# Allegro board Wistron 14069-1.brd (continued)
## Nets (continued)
M_B_DQS_DP2: CPU1.AP33 DIMM2.175 DIMM4.175
M_B_DQS_DP3: CPU1.AN28 DIMM2.186 DIMM4.186
M_B_DQS_DP4: CPU1.AN12 DIMM2.245 DIMM4.245
M_B_DQS_DP5: CPU1.AP8 DIMM2.256 DIMM4.256
M_B_DQS_DP6: CPU1.AL8 DIMM2.267 DIMM4.267
M_B_DQS_DP7: CPU1.AG7 DIMM2.278 DIMM4.278
M_B_ODT0: CPU1.AM16 DIMM4.87
M_B_ODT1: CPU1.AL16 DIMM4.91
M_B_ODT2: CPU1.AP15 DIMM2.87
M_B_ODT3: CPU1.AL15 DIMM2.91
M_BA_A_0: CPU1.AY13 DIMM1.81 DIMM3.81
M_BA_A_1: CPU1.AV15 DIMM1.224 DIMM3.224
M_BA_B_0: CPU1.AL18 DIMM2.81 DIMM4.81
M_BA_B_1: CPU1.AM18 DIMM2.224 DIMM4.224
M_BG_A_0: CPU1.AW23 DIMM1.63 DIMM3.63
M_BG_A_1: CPU1.AV23 DIMM1.207 DIMM3.207
M_BG_B_0: CPU1.AW28 DIMM2.63 DIMM4.63
M_BG_B_1: CPU1.AY28 DIMM2.207 DIMM4.207
M_PAR_A: CPU1.AY15 DIMM1.222 DIMM3.222
M_PAR_B: CPU1.AL20 DIMM2.222 DIMM4.222
M_VREF_DQ_DIM1: C2.1 C1206.1 CPU1.AC39 R1206.1
ME_CNTL: PCH1.AE44 R1506.1 R2059.1
ME_CNTL_1: Q2005.B R2059.2
ME_CNTL_2: Q2005.E R2060.2
MIC1_JD: AUDR1.3 D3001.2 R3013.1
MIC1_VREFO_L: R3008.1 U2701.28
MIC1_VREFO_R: R3011.1 U2701.32
MIC2-VREFO: D2906.3 U2701.30
MIC2_JD: AUDF1.5 R2909.2
MIC2_L: AUDF1.2 C2936.2 FL2906.2
MIC2_LL: FL2906.1 Q2902.6 R2932.2 R2948.2
MIC2_LL*: Q2902.2 R2950.2
MIC2_R: AUDF1.4 C2934.2 FL2907.2
MIC2_RR: FL2907.1 Q2902.3 R2941.2 R2949.2
MIC2_RR*: Q2902.5 R2951.2
MINI1_WAKE#: NGFFE1.55 R6106.2
MINI_CLKREQ#_WLAN_C: NGFFE1.53 R6107.2
MONO_C_L: C2920.1 R2921.2 SPK1.1
MONO_C_R: C2921.1 R2922.2 SPK1.3
MONO_L: C2735.2 R2921.1
MONO_R: C2736.2 R2922.1
MUTE: Q2704.C R2926.1 R2950.1 R2951.1 R2952.1 R2953.1 R3014.1 R3015.1 R3016.1 R3017.1 R3018.1 R3019.1
MUTE_C: Q2903.C R2920.1 SPK1.7
MUTE_INT: Q2903.B R2926.2
MUTE_R: Q2704.B R2708.2 R2712.1
MUTE_RR: C2721.1 C2722.1 Q2703.E R2708.1
NGFFE_ALERT#: PCH1.R36 R1505.1 R6118.1
NGFFE_ALERT#_R: NGFFE1.62 R6118.2
OC_LED_GREEN_C: LEDH2.11 LEDH2.13 Q23.6 R6424.2
OCL_PCH_N: PCH1.AM44 R472.1 R473.1 R1504.1
OPC_FUSEPRG: CPU1.AB38 TP_CPU13.1
P2402OV_EN: C6214.1 R866.2 R3418.2 U3402.2 U3402.4
PB_IN_N_1: C7921.2 R7976.1 R7977.2 SIO1.75
PCH_CLKRUN_N: PCH1.AW22 R2024.1
PCH_GPIO1: GPIO1.1 PCH1.AL35 R244.1 R813.1
PCH_GPIO2: GPIO2.1 PCH1.AJ39 R243.1 R814.1
PCH_HOT_R_N: PCH1.AT27 R2221.2 R2222.2
PCH_INTRUDER_N: PCH1.BE11 R1510.1
PCH_JTAG_TCK: PCH1.AN3 R2037.2 R9910.1
PCH_JTAG_TDI: PCH1.AP2 R452.2 R2040.1
PCH_JTAG_TDO: PCH1.AP1 R456.2 R2038.1
PCH_JTAG_TMS: PCH1.AR2 R454.2 R2043.1
PCH_JTAGX: PCH1.AR3 R2035.1 R2036.2
PCH_PORT80_LED: PCH1.BB41 R2214.2 R2215.2
PCH_POWER_VIN: PD5101.K PD5102.K PR5102.2 PR5103.2
PCH_PWROK: PCH1.AW11 R474.1 U401.D
PCH_RTCRST_PULLUP: C2006.2 CMOS1.2 PCH1.BC10 R2049.1
PCH_SATA_LED_N: Q6402.2 R1703.2 R6409.2
PCH_SATA_LED_NMOS: Q58.D Q6402.5 Q6402.6 R650.2 R6405.2
PCH_SATA_LED_R_N: PCH1.AD44 R1703.1
PCH_SPKR1: Q2002.B R2008.2
PCH_SRTCRSTB_PULLUP: C2001.2 PCH1.BB10 R2046.2
PCH_SUSCLK_WLAN: NGFFE1.50 R6108.2
PCH_SYSPWROK: C2002.1 D21.3 PCH1.AY1 R2011.2 R2012.2 R2014.2 R9908.1
PCH_WAKE_N: PCH1.BC13 PCIE1.B11 PCIE2.B11 PCIE16.B11 R2030.1 R6106.1 R6211.2
PCIE_RX_CON_N9: NGFFM1.43 R926.1
PCIE_RX_CON_N10: NGFFM1.29 R923.1
PCIE_RX_CON_N11: NGFFM1.17 R921.1
PCIE_RX_CON_N12: NGFFM1.5 R919.1
PCIE_RX_CON_P9: NGFFM1.41 R925.1
PCIE_RX_CON_P10: NGFFM1.31 R924.1
PCIE_RX_CON_P11: NGFFM1.19 R922.1
PCIE_RX_CON_P12: NGFFM1.7 R920.1
PCIE_RX_LAN_N5: C1605.2 U3101.18
PCIE_RX_LAN_P5: C1602.2 U3101.17
PCIE_RX_PCH_N5: C1605.1 PCH1.K19
PCIE_RX_PCH_N6: NGFFE1.43 PCH1.G22
PCIE_RX_PCH_N7: PCH1.L22 PCIE1.A17
PCIE_RX_PCH_N8: PCH1.K24 PCIE2.A17
PCIE_RX_PCH_N9: PCH1.G31 R926.2
PCIE_RX_PCH_N10: PCH1.G29 R923.2
PCIE_RX_PCH_N11: PCH1.L31 R921.2
PCIE_RX_PCH_N12: PCH1.G33 R919.2
PCIE_RX_PCH_P5: C1602.1 PCH1.L19
PCIE_RX_PCH_P6: NGFFE1.41 PCH1.E22
PCIE_RX_PCH_P7: PCH1.K22 PCIE1.A16
PCIE_RX_PCH_P8: PCH1.L24 PCIE2.A16
PCIE_RX_PCH_P9: PCH1.H31 R925.2
PCIE_RX_PCH_P10: PCH1.E29 R924.2
PCIE_RX_PCH_P11: PCH1.K31 R922.2
PCIE_RX_PCH_P12: PCH1.H33 R920.2
PCIE_TX_CON_N6: C1606.1 NGFFE1.37
PCIE_TX_CON_N7: C1607.1 PCIE1.B15
PCIE_TX_CON_N8: C1617.1 PCIE2.B15
PCIE_TX_CON_N9: C473.2 NGFFM1.47
PCIE_TX_CON_N10: C471.2 NGFFM1.35
PCIE_TX_CON_N11: C469.2 NGFFM1.23
PCIE_TX_CON_N12: C467.2 NGFFM1.11
PCIE_TX_CON_P6: C1601.1 NGFFE1.35
PCIE_TX_CON_P7: C1604.1 PCIE1.B14
PCIE_TX_CON_P8: C1618.1 PCIE2.B14
PCIE_TX_CON_P9: C474.2 NGFFM1.49
PCIE_TX_CON_P10: C472.2 NGFFM1.37
PCIE_TX_CON_P11: C470.2 NGFFM1.25
PCIE_TX_CON_P12: C468.2 NGFFM1.13
PCIE_TX_LAN_N5: C1608.1 U3101.14
PCIE_TX_LAN_P5: C1603.1 U3101.13
PCIE_TX_PCH_N5: C1608.2 PCH1.D22
PCIE_TX_PCH_N6: C1606.2 PCH1.B22
PCIE_TX_PCH_N7: C1607.2 PCH1.C23
PCIE_TX_PCH_N8: C1617.2 PCH1.C24
PCIE_TX_PCH_N9: C473.1 PCH1.C31
PCIE_TX_PCH_N10: C471.1 PCH1.C32
PCIE_TX_PCH_N11: C469.1 PCH1.C33
PCIE_TX_PCH_N12: C467.1 PCH1.B35
PCIE_TX_PCH_P5: C1603.2 PCH1.C22
PCIE_TX_PCH_P6: C1601.2 PCH1.A23
PCIE_TX_PCH_P7: C1604.2 PCH1.B23
PCIE_TX_PCH_P8: C1618.2 PCH1.B24
PCIE_TX_PCH_P9: C474.1 PCH1.B31
PCIE_TX_PCH_P10: C472.1 PCH1.B32
PCIE_TX_PCH_P11: C470.1 PCH1.B33
PCIE_TX_PCH_P12: C468.1 PCH1.A35
PCIEX16_PRSNT1_N: PCIE16.A1 R9301.2
PCIEX16_PRSNT2_N: PCIE16.B17 PCIE16.B31 PCIE16.B48 PCIE16.B81 R9304.2
PCIEX16_PRSNT2_R1_N: R1801.1 R1812.1 R9304.1
PCIEX16_PRSNT2_R2_N: PCH1.BD32 R1801.2
PCIRST1#: R7924.2 RN7909.2(A) SIO1.33
PCIRST2#: RN7909.1(A) SIO1.34
PECI_CPU: CPU1.G7 R1701.1 R2475.1
PECI_PCH: C1701.1 PCH1.AL3 R1701.2 R1706.1
PECI_SIO_R: R2475.2 SIO1.55
PEG_CLK1_WLAN: NGFFE1.47 PCH1.L5
PEG_CLK1_WLAN#: NGFFE1.49 PCH1.L7
PEG_CLK2_LAN: PCH1.F2 U3101.15
PEG_CLK2_LAN#: PCH1.D3 U3101.16
PEG_CLK3_SSD: NGFFM1.55 PCH1.G4
PEG_CLK3_SSD#: NGFFM1.53 PCH1.E5
PEG_CLK4_PCH: PCH1.E6 PCIE2.A13
PEG_CLK4_PCH#: PCH1.D5 PCIE2.A14
PEG_CLK5_PCH: PCH1.D7 PCIE1.A13
PEG_CLK5_PCH#: PCH1.D8 PCIE1.A14
PEG_CLK8_PCH: PCH1.W11 PCIE16.A13
PEG_CLK8_PCH#: PCH1.W10 PCIE16.A14
PEG_CLKREQ1_WLAN#: PCH1.AW24 R1809.1 R6107.1
PEG_CLKREQ2_LAN#: PCH1.AT24 R1810.1 R3108.2
PEG_CLKREQ3_M2#: PCH1.BC24 R1811.1 R6212.2
PEG_PCIEX1_CLKREQ5: PCH1.BE25 PCIE1.B17 R1814.1
PEG_PCIEX1_CLKREQ6: PCH1.AT33 PCIE2.B17 R1815.1
PEG_RCOMP_CPU: CPU1.L7 R302.2
PEG_RCOMPN_CPU: PCH1.B18 R1608.1
PEG_RCOMPP_CPU: PCH1.C17 R1608.2
PEG_RX_CPU_N0: CPU1.B7 PCIE16.A17
PEG_RX_CPU_N1: CPU1.C6 PCIE16.A22
PEG_RX_CPU_N2: CPU1.D5 PCIE16.A26
PEG_RX_CPU_N3: CPU1.E4 PCIE16.A30
PEG_RX_CPU_N4: CPU1.F5 PCIE16.A36
PEG_RX_CPU_N5: CPU1.G4 PCIE16.A40
PEG_RX_CPU_N6: CPU1.H5 PCIE16.A44
PEG_RX_CPU_N7: CPU1.J4 PCIE16.A48
PEG_RX_CPU_N8: CPU1.K5 PCIE16.A53
PEG_RX_CPU_N9: CPU1.L4 PCIE16.A57
PEG_RX_CPU_N10: CPU1.M5 PCIE16.A61
PEG_RX_CPU_N11: CPU1.N4 PCIE16.A65
PEG_RX_CPU_N12: CPU1.P5 PCIE16.A69
PEG_RX_CPU_N13: CPU1.R4 PCIE16.A73
PEG_RX_CPU_N14: CPU1.T5 PCIE16.A77
PEG_RX_CPU_N15: CPU1.U4 PCIE16.A81
PEG_RX_CPU_P0: CPU1.B8 PCIE16.A16
PEG_RX_CPU_P1: CPU1.C7 PCIE16.A21
PEG_RX_CPU_P2: CPU1.D6 PCIE16.A25
PEG_RX_CPU_P3: CPU1.E5 PCIE16.A29
PEG_RX_CPU_P4: CPU1.F6 PCIE16.A35
PEG_RX_CPU_P5: CPU1.G5 PCIE16.A39
PEG_RX_CPU_P6: CPU1.H6 PCIE16.A43
PEG_RX_CPU_P7: CPU1.J5 PCIE16.A47
PEG_RX_CPU_P8: CPU1.K6 PCIE16.A52
PEG_RX_CPU_P9: CPU1.L5 PCIE16.A56
PEG_RX_CPU_P10: CPU1.M6 PCIE16.A60
PEG_RX_CPU_P11: CPU1.N5 PCIE16.A64
PEG_RX_CPU_P12: CPU1.P6 PCIE16.A68
PEG_RX_CPU_P13: CPU1.R5 PCIE16.A72
PEG_RX_CPU_P14: CPU1.T6 PCIE16.A76
PEG_RX_CPU_P15: CPU1.U5 PCIE16.A80
PEG_TX_CON_N0: C9303.2 PCIE16.B15
PEG_TX_CON_N1: C9305.2 PCIE16.B20
PEG_TX_CON_N2: C9307.2 PCIE16.B24
PEG_TX_CON_N3: C9309.2 PCIE16.B28
PEG_TX_CON_N4: C9314.2 PCIE16.B34
PEG_TX_CON_N5: C9316.2 PCIE16.B38
PEG_TX_CON_N6: C9318.2 PCIE16.B42
PEG_TX_CON_N7: C9320.2 PCIE16.B46
PEG_TX_CON_N8: C9324.2 PCIE16.B51
PEG_TX_CON_N9: C9326.2 PCIE16.B55
PEG_TX_CON_N10: C9328.2 PCIE16.B59
PEG_TX_CON_N11: C9332.2 PCIE16.B63
PEG_TX_CON_N12: C9334.2 PCIE16.B67
PEG_TX_CON_N13: C9336.2 PCIE16.B71
PEG_TX_CON_N14: C9338.2 PCIE16.B75
PEG_TX_CON_N15: C9340.2 PCIE16.B79
PEG_TX_CON_P0: C9302.2 PCIE16.B14
PEG_TX_CON_P1: C9304.2 PCIE16.B19
PEG_TX_CON_P2: C9306.2 PCIE16.B23
PEG_TX_CON_P3: C9308.2 PCIE16.B27
PEG_TX_CON_P4: C9313.2 PCIE16.B33
PEG_TX_CON_P5: C9315.2 PCIE16.B37
PEG_TX_CON_P6: C9317.2 PCIE16.B41
PEG_TX_CON_P7: C9319.2 PCIE16.B45
PEG_TX_CON_P8: C9323.2 PCIE16.B50
PEG_TX_CON_P9: C9325.2 PCIE16.B54
PEG_TX_CON_P10: C9327.2 PCIE16.B58
PEG_TX_CON_P11: C9331.2 PCIE16.B62
PEG_TX_CON_P12: C9333.2 PCIE16.B66
PEG_TX_CON_P13: C9335.2 PCIE16.B70
PEG_TX_CON_P14: C9337.2 PCIE16.B74
PEG_TX_CON_P15: C9339.2 PCIE16.B78
PEG_TX_CPU_N0: C9303.1 CPU1.A6
PEG_TX_CPU_N1: C9305.1 CPU1.B5
PEG_TX_CPU_N2: C9307.1 CPU1.C4
PEG_TX_CPU_N3: C9309.1 CPU1.D3
PEG_TX_CPU_N4: C9314.1 CPU1.E2
PEG_TX_CPU_N5: C9316.1 CPU1.F3
PEG_TX_CPU_N6: C9318.1 CPU1.G2
PEG_TX_CPU_N7: C9320.1 CPU1.H3
PEG_TX_CPU_N8: C9324.1 CPU1.J2
PEG_TX_CPU_N9: C9326.1 CPU1.K3
PEG_TX_CPU_N10: C9328.1 CPU1.L2
PEG_TX_CPU_N11: C9332.1 CPU1.M3
PEG_TX_CPU_N12: C9334.1 CPU1.N2
PEG_TX_CPU_N13: C9336.1 CPU1.P3
PEG_TX_CPU_N14: C9338.1 CPU1.R1
PEG_TX_CPU_N15: C9340.1 CPU1.T3
PEG_TX_CPU_P0: C9302.1 CPU1.A5
PEG_TX_CPU_P1: C9304.1 CPU1.B4
PEG_TX_CPU_P2: C9306.1 CPU1.C3
PEG_TX_CPU_P3: C9308.1 CPU1.D2
PEG_TX_CPU_P4: C9313.1 CPU1.E1
PEG_TX_CPU_P5: C9315.1 CPU1.F2
PEG_TX_CPU_P6: C9317.1 CPU1.G1
PEG_TX_CPU_P7: C9319.1 CPU1.H2
PEG_TX_CPU_P8: C9323.1 CPU1.J1
PEG_TX_CPU_P9: C9325.1 CPU1.K2
PEG_TX_CPU_P10: C9327.1 CPU1.L1
PEG_TX_CPU_P11: C9331.1 CPU1.M2
PEG_TX_CPU_P12: C9333.1 CPU1.N1
PEG_TX_CPU_P13: C9335.1 CPU1.P2
PEG_TX_CPU_P14: C9337.1 CPU1.R2
PEG_TX_CPU_P15: C9339.1 CPU1.T2
PLT_WLAN_RST_C: NGFFE1.52 R6109.1
PLTRST#_PCH: C9420.1 C9422.1 DBGH1.10 PCIE1.A11 PCIE2.A11 R1521.2 R6109.2 R6213.2 R7939.2 R9302.1 SATAEX1.P2
PLTRST#_PCH_R: PCH1.BB27 R1521.1
PLTRST#_R: PCIE16.A11 R9302.2
PLTRST*_SIO: R7939.1 SIO1.49
PLTRST_CPU_N: CPU1.E7 PCH1.AK2 R9919.1
PLTRST_LAN_N: R3107.2 R7924.1
PLTRST_LAN_N_R: C3113.1 R3107.1 U3101.19
PM_DOWN_CPU: CPU1.D8 R422.2
PM_DOWN_PCH: PCH1.AH2 R422.1
PM_SLP_S3#_3: D4.K R91.2 SIO1.79 TP168.1
PM_SYNC_CPU: CPU1.E8 R1705.2
PM_SYNC_PCH: PCH1.AJ4 R1705.1
PRIM_XDP_JTAG_TCK_R: R9910.2 XDP1.55
PROC_TRIGIN_CPU: CPU1.D1 R2106.2
PROC_TRIGIN_PCH: PCH1.AL2 R2106.1
PROC_TRIGOUT_CPU: CPU1.B3 R902.2
PROC_TRIGOUT_PCH: PCH1.AK1 R902.1
PROCHOT#_CPU: CPU1.C39 R467.2
PROCHOT#_R: PR4678.2 PU4601.23 R421.1 R467.1
PS_ON_N: Q98.G R4303.2 R4305.2 R7919.2 SIO1.76
PWM1: PU4601.52 PU4716.1
PWM1A: PU4601.47 PU4804.1
PWM2: PU4601.51 PU4709.1
PWM2A: PU4601.46 PU4809.1
PWM3: PU4601.53 PU4713.1
PWM4: PU4601.50 PU4719.1
PWM_LED_N_C: Q25.6 R652.1
PWR_2D5V_EN: PR977.2 PU51.5
PWR_2D5V_FB: PC5038.2 PC5039.1 PR5143.2 PR5145.1 PU51.6
PWR_2D5V_FB_N: PC5039.2 PR5146.1
PWR_2D5V_LX: PL12.1 PR302.1 PU51.1 PU51.2 PU51.3
PWR_2D5V_PVIN: PC5033.1 PC5034.1 PR5024.2 PR5025.2 PR5142.1 PU51.9 PU51.10
PWR_2D5V_SNB: PC301.1 PR302.2
PWR_2D5V_SVIN: PC5035.1 PR5142.2 PU51.8
PWR_2D5V_VPP: PC5036.1 PC5037.1 PC5038.1 PL12.2 PR5026.1 PR5027.1 PR5143.1
PWR_+0P95V: PC5301.1 PC5306.1 PC5309.1 PL5301.2 PR5310.1 PR5313.1 PR5314.1 PR5315.1 PR5321.1 TC5301.1
PWR_+0P95V_BOOT: PR5305.1 PU5301.10
PWR_+0P95V_BOOT_R: PC5305.1 PR5305.2
PWR_+0P95V_CS: PR5307.1 PU5301.2
PWR_+0P95V_EN: PC5311.1 PR5301.1 PU5301.3
PWR_+0P95V_FB: PC5309.2 PR5312.2 PR5316.1 PU5301.4
PWR_+0P95V_LGATE: PU5301.6 PU5303.4
PWR_+0P95V_PHASE: PC5305.2 PL5301.1 PR5309.1 PU5301.8 PU5302.1 PU5302.2 PU5302.3 PU5303.5 PU5303.6 PU5303.7 PU5303.8
PWR_+0P95V_RF: PR5308.1 PU5301.5
PWR_+0P95V_SNB: PC5308.1 PR5309.2
PWR_+0P95V_UG_R: PR5306.2 PU5302.4
PWR_+0P95V_UGATE: PR5306.1 PU5301.9
PWR_+0P95V_VCC: PC5307.1 PR5311.1 PU5301.7
PWR_+0P95V_VIN: PC5302.1 PC5303.1 PC5304.1 PC5310.1 PR5302.1 PR5303.1 PU5302.5 PU5302.6 PU5302.7 PU5302.8
PWR_+1V2_DDR: PC5007.1 PG5001.1 PL5001.2 PR5001.1 PR5016.1 PR5017.1 PR5019.1 PR5020.1 PR5021.1 PR5022.1 PR5023.1 TC5002.1 TC5003.1
PWR_+PCH_1V0: PC5101.1 PG5101.1 PL5101.2 PR5101.1 PR5114.1 PR5115.1 PR5116.1 PR5117.1 PT5107.1
PWR_+PCH_1V0_BOOT: PR5106.2 PU5101.10
PWR_+PCH_1V0_BOOT1: PC5105.1 PR5106.1
PWR_+PCH_1V0_CS: PR5109.1 PU5101.2
PWR_+PCH_1V0_EN: PC5111.2 PR5105.2 PR5108.2 PU5101.3
PWR_+PCH_1V0_FB: PC5110.2 PR5113.2 PR5118.1 PU5101.4
PWR_+PCH_1V0_FB1: PC5110.1 PG5101.2 PR5113.1
PWR_+PCH_1V0_LGATE: PU5101.6 PU5103.4
PWR_+PCH_1V0_PG: PC5106.2 PR5104.2 PU5101.1
PWR_+PCH_1V0_PHASE: PC5105.2 PL5101.1 PR5111.1 PU5101.8 PU5102.1 PU5102.2 PU5102.3 PU5103.5 PU5103.6 PU5103.7 PU5103.8
PWR_+PCH_1V0_RF: PR5110.1 PU5101.5
PWR_+PCH_1V0_SNB: PC5108.1 PR5111.2
PWR_+PCH_1V0_UG1: PR5107.2 PU5102.4
PWR_+PCH_1V0_UGATE: PR5107.1 PU5101.9
PWR_+PCH_1V0_VCC: PC5109.1 PR5112.1 PU5101.7
PWR_+PCH_1V0_VIN: PC5102.1 PC5103.1 PR5102.1 PR5103.1 PT5101.1 PU5102.5 PU5102.6 PU5102.7 PU5102.8
PWR_+VCORE_VIN: PC4701.1 PC4702.1 PC4707.1 PC4711.1 PC4716.1 PC4717.1 PC4735.1 PC4736.1 PR4662.1 PR4668.1 PR4706.2 PR4711.2 PR4718.2 PR4720.1 PR4721.1 PR4722.1 PR4723.1 PR4724.1 PR4725.1 PR5456.2 PT4702.1 PT4707.1 PT4708.1 PT4709.1 PU4701.5 PU4701.6 PU4701.7 PU4701.8 PU4702.5 PU4702.6 PU4702.7 PU4702.8 PU4703.5 PU4703.6 PU4703.7 PU4703.8 PU4704.5 PU4704.6 PU4704.7 PU4704.8 PU4708.5 PU4708.6 PU4708.7 PU4708.8 PU4712.5 PU4712.6 PU4712.7 PU4712.8 PU4718.5 PU4718.6 PU4718.7 PU4718.8 PU4721.5 PU4721.6 PU4721.7 PU4721.8
PWR_+VGT_VIN: PC4801.1 PC4803.1 PC4807.1 PC4808.1 PR4802.1 PR4803.1 PR4805.1 PR4806.1 PR4807.1 PR4811.2 PR4817.2 PT4802.1 PT4807.1 PU4802.5 PU4802.6 PU4802.7 PU4802.8 PU4803.5 PU4803.6 PU4803.7 PU4803.8 PU4807.5 PU4807.6 PU4807.7 PU4807.8 PU4808.5 PU4808.6 PU4808.7 PU4808.8
PWR_BTNJ_C: LEDH1.6 R6403.2 R6404.1
PWR_DDR_BT1: PC5005.1 PR5010.1
PWR_LED_G: C6405.2 LEDH2.2 R6417.2
PWR_LED_T: C6404.2 LEDH2.7 R6415.2
PWR_LED_YELLOW_C: LEDH2.12 Q23.3 R6426.2
PWR_LED_YELLOW_C2: LEDH2.14 Q6807.D R6427.2
PWR_LEDC1: Q6403.B R6408.1
PWR_LEDC1_D: Q6401.D R6406.2 R6408.2
PWR_LEDC2: Q6405.B R6414.1
PWR_LEDC2_D: Q6406.D R6413.2 R6414.2 R6416.2
PWR_LEDC3: Q6407.B R6416.1
PWR_LEDJ_C: C6401.1 C6403.2 LEDH1.2 R6410.2
PWR_LEDJ_G: Q6407.C R6417.1
PWR_LEDJ_P: Q6403.C R6410.1
PWR_LEDJ_T: Q6405.C R6415.1
PWR_RT3607_ALTER: PR4692.2 PU4601.24
PWR_RT3607_COMP: PC4610.1 PR4602.1 PU4601.11
PWR_RT3607_COMP_L: PR4602.2 PR4603.1
PWR_RT3607_COMPA: PC4630.1 PR4629.1 PU4601.34
PWR_RT3607_COMPA_L: PR4629.2 PR4630.1
PWR_RT3607_DVD: PC4666.2 PR4683.1 PR4684.1 PU4601.45
PWR_RT3607_FB: PC4602.1 PC4610.2 PR4603.2 PU4601.10 R4606.1
PWR_RT3607_FB2_C: PC4602.2 PR5413.2 R4606.2
PWR_RT3607_FBA: PC4630.2 PC4631.1 PR4630.2 PR4671.1 PU4601.35
PWR_RT3607_FBA2_C: PC4631.2 PR4633.2 PR4671.2
PWR_RT3607_IBIAS: PR4601.1 PU4601.31
PWR_RT3607_IMON: PR4656.2 PU4601.20
PWR_RT3607_IMONA: PR4632.2 PU4601.22
PWR_RT3607_ISEN1N: PR4611.1 PU4601.4
PWR_RT3607_ISEN2N: PR4623.1 PU4601.7
PWR_RT3607_ISEN3N: PR4622.1 PU4601.3
PWR_RT3607_ISEN4N: PR4621.1 PR4693.2 PR4694.1 PU4601.8
PWR_RT3607_ISENA1N: PR4639.1 PU4601.39
PWR_RT3607_ISENA2N: PR4652.1 PU4601.36
PWR_RT3607_ISENA3N: PR4665.1 PU4601.40 PU4601.41
PWR_RT3607_PS4: PR4695.1 PU4601.49
PWR_RT3607_RGNDA: PC4643.2 PC4644.1 PR4688.2 PR4689.2 PU4601.32
PWR_RT3607_SET1: PR4641.2 PR4642.1 PU4601.14 TP_SET1.1
PWR_RT3607_SET1_N: PR4642.2 PR4643.1
PWR_RT3607_SET1_N#: PR4640.2 PR4641.1
PWR_RT3607_SET2: PG4699.1 PR4645.2 PR4667.1 PU4601.15 TP_SET2.1
PWR_RT3607_SET2_N: PR4647.1 PR4667.2
PWR_RT3607_SET2_N#: PR4644.2 PR4645.1
PWR_RT3607_SET3: PR4650.1 PR4658.2 PU4601.17 TP_SET3.1
PWR_RT3607_SET3_N: PR4650.2 PR5458.2
PWR_RT3607_SET3_N#: PR4651.2 PR4658.1
PWR_RT3607_SETA1: PR4653.2 PR4654.1 PU4601.18 TP_SET7.1
PWR_RT3607_SETA1_N: PR4654.2 PR4655.1
PWR_RT3607_SETA1_N#: PR4653.1 PR4687.2
PWR_RT3607_SETA2: PR4657.1 PR4666.2 PU4601.19 TP_SET8.1
PWR_RT3607_SETA2_N: PR4657.2 PR4659.2
PWR_RT3607_SETA2_N#: PR4666.1 PR4686.2
PWR_RT3607_TONSET: PR4663.2 PU4601.55 TP_SET6.1
PWR_RT3607_TONSET_R: PC4637.2 PR4662.2 PR4663.1
PWR_RT3607_TONSETA: PR4661.2 PU4601.43 TP_SET5.1
PWR_RT3607_TONSETA_R: PC4636.2 PR4661.1 PR4668.2
PWR_RT3607_TSEN: PN4603.2 PR4672.2 PU4601.1
PWR_RT3607_TSEN_R1: PR4672.1 PR4673.2
PWR_RT3607_TSEN_R2: PN4603.1 PR4674.2
PWR_RT3607_TSENA: PN4604.2 PR4676.2 PU4601.42
PWR_RT3607_TSENA_R1: PR4675.2 PR4676.1
PWR_RT3607_TSENA_R2: PN4604.1 PR4677.2
PWR_RT3607_VCC: PC4632.1 PR4604.2 PU4601.29
PWR_RT3607_VCLK: PR4670.1 PU4601.26
PWR_RT3607_VDIO: PR4691.1 PU4601.25
PWR_RT3607_VREF: PN4605.2 PN4606.2 PR4640.1 PR4644.1 PR4646.1 PR4651.1 PR4664.1 PR4686.1 PR4687.1 PR4690.1 PU4601.21
PWR_RT3607_VREF_1: PR4646.2 PR4649.1
PWR_RT3607_VREF_2: PR4632.1 PR4648.2 PR4649.2
PWR_RT3607_VREF_3: PN4605.1 PR4648.1
PWR_RT3607_VREF_4: PR4660.1 PR4690.2
PWR_RT3607_VREF_5: PR4656.1 PR4660.2 PR4669.2
PWR_RT3607_VREF_6: PN4606.1 PR4669.1
PWR_RT3607_VREF_R: PC4645.1 PR4664.2
PWR_RT9624F_BST1: PR4702.2 PU4716.8
PWR_RT9624F_BST1A: PR4804.2 PU4804.8
PWR_RT9624F_BST1AR: PC4802.1 PR4804.1
PWR_RT9624F_BST1R: PC4703.1 PR4702.1
PWR_RT9624F_BST2: PR4707.2 PU4709.8
PWR_RT9624F_BST2A: PR4812.2 PU4809.8
PWR_RT9624F_BST2AR: PC4806.1 PR4812.1
PWR_RT9624F_BST2R: PC4706.1 PR4707.1
PWR_RT9624F_BST3R: PC4710.1 PR4713.1
PWR_RT9624F_BST4R: PC4734.1 PR4755.1
PWR_RT9624F_DRVH1: PR4703.2 PU4716.7
PWR_RT9624F_DRVH1A: PR4801.2 PU4804.7
PWR_RT9624F_DRVH2: PR4708.2 PU4709.7
PWR_RT9624F_DRVH2A: PR4813.2 PU4809.7
PWR_RT9624F_DRVH3: PR4714.2 PU4713.7
PWR_RT9624F_DRVH4: PR4752.2 PU4719.7
PWR_RT9624F_DRVL1: PU4705.4 PU4706.4 PU4716.5
PWR_RT9624F_DRVL2: PU4709.5 PU4710.4 PU4711.4
PWR_RT9624F_DRVL3: PU4713.5 PU4714.4 PU4715.4
PWR_RT9624F_DRVL4: PU4707.4 PU4717.4 PU4719.5
PWR_RT9624F_DRVLA1: PU4804.5 PU4805.4 PU4806.4
PWR_RT9624F_DRVLA2: PU4801.4 PU4809.5 PU4810.4
PWR_RT9624F_H1R: PR4703.1 PR4704.1 PU4702.4 PU4703.4
PWR_RT9624F_H2R: PR4708.1 PR4709.1 PU4708.4 PU4721.4
PWR_RT9624F_H3R: PR4714.1 PR4715.1 PU4701.4 PU4712.4
PWR_RT9624F_H4R: PR4752.1 PR5453.1 PU4704.4 PU4718.4
PWR_RT9624F_HR1A: PR4801.1 PR4808.1 PU4802.4 PU4803.4
PWR_RT9624F_HR2A: PR4813.1 PR4814.1 PU4807.4 PU4808.4
PWR_RT9624F_SNB1: PC4705.1 PR4705.2
PWR_RT9624F_SNB1A: PC4804.1 PR4810.2
PWR_RT9624F_SNB2: PC4709.1 PR4712.2
PWR_RT9624F_SNB2A: PC4810.1 PR4816.2
PWR_RT9624F_SNB3: PC4713.1 PR4717.2
PWR_RT9624F_SNB4: PC4737.1 PR4754.2
PWR_RT9624F_SW1: PC4703.2 PG4702.1 PL4701.1 PR4704.2 PR4705.1 PU4702.1 PU4702.2 PU4702.3 PU4703.1 PU4703.2 PU4703.3 PU4705.5 PU4705.6 PU4705.7 PU4705.8 PU4706.5 PU4706.6 PU4706.7 PU4706.8 PU4716.6
PWR_RT9624F_SW1A: PC4802.2 PG4801.1 PL4801.1 PR4808.2 PR4810.1 PU4802.1 PU4802.2 PU4802.3 PU4803.1 PU4803.2 PU4803.3 PU4804.6 PU4805.5 PU4805.6 PU4805.7 PU4805.8 PU4806.5 PU4806.6 PU4806.7 PU4806.8
PWR_RT9624F_SW2: PC4706.2 PG4701.1 PL4702.1 PR4709.2 PR4712.1 PU4708.1 PU4708.2 PU4708.3 PU4709.6 PU4710.5 PU4710.6 PU4710.7 PU4710.8 PU4711.5 PU4711.6 PU4711.7 PU4711.8 PU4721.1 PU4721.2 PU4721.3
PWR_RT9624F_SW2A: PC4806.2 PG4803.1 PL4802.1 PR4814.2 PR4816.1 PU4801.5 PU4801.6 PU4801.7 PU4801.8 PU4807.1 PU4807.2 PU4807.3 PU4808.1 PU4808.2 PU4808.3 PU4809.6 PU4810.5 PU4810.6 PU4810.7 PU4810.8
PWR_RT9624F_SW3: PC4710.2 PG4705.1 PL4703.1 PR4715.2 PR4717.1 PU4701.1 PU4701.2 PU4701.3 PU4712.1 PU4712.2 PU4712.3 PU4713.6 PU4714.5 PU4714.6 PU4714.7 PU4714.8 PU4715.5 PU4715.6 PU4715.7 PU4715.8
PWR_RT9624F_SW4: PC4734.2 PG5203.1 PL4704.1 PR4754.1 PR5453.2 PU4704.1 PU4704.2 PU4704.3 PU4707.5 PU4707.6 PU4707.7 PU4707.8 PU4717.5 PU4717.6 PU4717.7 PU4717.8 PU4718.1 PU4718.2 PU4718.3 PU4719.6
PWR_RT9624F_VCC1: PC4704.1 PR4706.1 PR4742.2 PU4716.4
PWR_RT9624F_VCC1A: PC4805.1 PR4811.1 PR4826.2 PU4804.4
PWR_RT9624F_VCC2: PC4708.1 PR4711.1 PR4744.2 PU4709.4
PWR_RT9624F_VCC2A: PC4809.1 PR4817.1 PR4828.2 PU4809.4
PWR_RT9624F_VCC3: PC4712.1 PR4718.1 PR4746.2 PU4713.4
PWR_RT9624F_VCC4: PC5438.1 PR4748.2 PR5456.1 PU4719.4
PWR_VCCSA_BOOT: PR5205.1 PU5202.4
PWR_VCCSA_BOOT_R: PC5205.1 PR5205.2
PWR_VCCSA_COMP: PC5207.1 PC5208.1 PU5202.8
PWR_VCCSA_COMP_A: PC5209.2 PR5215.1
PWR_VCCSA_COMP_R: PC5207.2 PC5268.1 PR5209.1
PWR_VCCSA_CSN: PC5210.2 PC5211.1 PG5202.2 PR5212.2 PU5202.12
PWR_VCCSA_CSP: PC5210.1 PR5201.2 PR5212.1 PU5202.13
PWR_VCCSA_CSP_R: PG5201.2 PR5201.1
PWR_VCCSA_EN: PR5207.1 PU5202.14 U5203.D
PWR_VCCSA_FB: PC5208.2 PC5209.1 PC5268.2 PR5209.2 PR5210.1 PR5211.1 PR5213.1 PU5202.9
PWR_VCCSA_LG: PU5201.4 PU5202.2
PWR_VCCSA_LX: PC5205.2 PG5201.1 PL5203.1 PR5208.1 PU5201.5 PU5201.6 PU5201.7 PU5201.8 PU5202.3 PU5203.1 PU5203.2 PU5203.3
PWR_VCCSA_SNB: PC5201.1 PR5208.2
PWR_VCCSA_UG: PR5206.1 PU5202.5
PWR_VCCSA_UG_R: PR5206.2 PU5203.4
PWR_VCCSA_VCC: PC5203.1 PR5203.2 PU5202.15
PWR_VCCSA_VCCP: PC5202.1 PR5202.2 PU5202.1
PWR_VCCSA_VIN: PC5204.1 PR5217.1 PR5218.1 PR5219.1 PT5201.1 PU5203.5 PU5203.6 PU5203.7 PU5203.8
PWR_VCCSA_VSEN: PR5210.2 PU5202.10
PWR_VDDQ_DDR_BOOT: PR5010.2 PU5002.18
PWR_VDDQ_DDR_CS: PR5003.2 PU5002.13
PWR_VDDQ_DDR_FB: PC5013.2 PR5015.2 PR5018.1 PU5002.6
PWR_VDDQ_DDR_FB1: PC5013.1 PG5001.2 PR5015.1
PWR_VDDQ_DDR_LDOIN: PC5006.1 PR5021.2 PU5002.19
PWR_VDDQ_DDR_LGATE: PU5001.4 PU5002.15
PWR_VDDQ_DDR_PHASE: PC5005.2 PL5001.1 PR5012.1 PU5001.5 PU5001.6 PU5001.7 PU5001.8 PU5002.16 PU5003.1 PU5003.2 PU5003.3
PWR_VDDQ_DDR_SNB: PC5011.1 PR5012.2
PWR_VDDQ_DDR_TON: PR5008.2 PU5002.9
PWR_VDDQ_DDR_UG1: PR5011.1 PU5003.4
PWR_VDDQ_DDR_UGATE: PR5011.2 PU5002.17
PWR_VDDQ_DDR_VDD: PC5003.1 PR5002.2 PR5003.1 PU5002.11
PWR_VDDQ_DDR_VDDQ: PR5001.2 PU5002.5
PWR_VDDQ_DDR_VIN: PC5004.1 PC5020.1 PC5427.1 PD5001.K PD5002.K PR5008.1 PT5004.1 PU5003.5 PU5003.6 PU5003.7 PU5003.8
PWR_VDDQ_DDR_VTTREF: PC5012.1 PU5002.4
PWRBTN_N: C6402.1 R6404.2 R7976.2
PWRDOWN_Q: R544.2 U27.2 U27.5 U28.5 U28.6
PWRGD3V_150MS: C7904.1 R2014.1 R7929.2 R7943.1
PWRGD_PS: ATX1.8 C4301.1 C4306.2 R3525.2 R4306.2 SIO1.19
PWRLED_2: L6401.1 LEDH2.5
PWROK3_1: R7922.2 SIO1.32
PWROK3_1_R: R7922.1 R7928.2 R7929.1
PWRRT9624F_BST3: PR4713.2 PU4713.8
PWRRT9624F_BST4: PR4755.2 PU4719.8
Q64_PIN2: Q5702.2 R5705.2 R5709.1
R_USBEN: R2930.2 R2935.1 R2938.2
R_USBEN1: C2912.1 R2935.2 R3821.1 U3601.4 U3605.4
R_USBEN1_R: C3142.1 Q3402.G R3112.2
R_USBEN2: C3811.1 R3821.2 U3606.4
RSMRST_SIO_N: PCH1.BA11 R2031.2 R2067.1 R9902.1 RN7905.1(A) SIO1.85
RSVD_AB13: PCH1.AB13 TP_PCH_AB13.1
RSVD_K13: CPU1.K13 R901.1
RT3607_PS4_RIGHTLINE: PR4695.2 PR4741.2 PR4742.1 PR4743.2 PR4744.1 PR4745.2 PR4746.1 PR4747.2 PR4748.1 PR4825.2 PR4826.1 PR4827.2 PR4828.1 PU4709.3 PU4713.3 PU4716.3 PU4719.3 PU4804.3 PU4809.3 TP_SET4.1
RTCEXT_CAP: C2101.1 PCH1.BA26
RTL_ISOLATE: C3121.1 Q3103.2 R3113.1 R3120.2
RTL_ISOLATE_R: Q3103.5 Q3103.6 R3114.1
S3_VTT_CTNL: R4018.1 R4019.2 R4020.2 U4002.3
S4_VPP_OR: Q72.5 R990.1
S4_VPP_OR_R: C707.1 R879.1 R884.2 R990.2
SATA_LED_OUT: LEDH1.3 Q6402.3 R6411.2
SATA_RX_C_N2: C6006.1 EL6002.4
SATA_RX_C_N3: C6008.1 EL6004.4
SATA_RX_C_N4: C6012.1 EL6005.4
SATA_RX_C_N5: C6016.1 EL6007.4
SATA_RX_C_P2: C6007.1 EL6002.3
SATA_RX_C_P3: C6009.1 EL6004.3
SATA_RX_C_P4: C6011.1 EL6005.3
SATA_RX_C_P5: C6015.1 EL6007.3
SATA_RX_CON_N2: C6006.2 SATA2.5 SATAEX1.S5
SATA_RX_CON_N3: C6008.2 SATA3.5 SATAEX1.S12
SATA_RX_CON_N4: C6012.2 SATA4.5
SATA_RX_CON_N5: C6016.2 SATA5.5
SATA_RX_CON_P2: C6007.2 SATA2.6 SATAEX1.S6
SATA_RX_CON_P3: C6009.2 SATA3.6 SATAEX1.S13
SATA_RX_CON_P4: C6011.2 SATA4.6
SATA_RX_CON_P5: C6015.2 SATA5.6
SATA_RX_PCH_N2: EL6002.1 PCH1.F41
SATA_RX_PCH_N3: EL6004.1 PCH1.D43
SATA_RX_PCH_N4: EL6005.1 PCH1.H42
SATA_RX_PCH_N5: EL6007.1 PCH1.K37
SATA_RX_PCH_P2: EL6002.2 PCH1.E41
SATA_RX_PCH_P3: EL6004.2 PCH1.E42
SATA_RX_PCH_P4: EL6005.2 PCH1.H40
SATA_RX_PCH_P5: EL6007.2 PCH1.G37
SATA_TX_C_N2: C6002.1 EL6001.3
SATA_TX_C_N3: C6005.1 EL6003.3
SATA_TX_C_N4: C6013.1 EL6006.3
SATA_TX_C_N5: C6017.1 EL6008.3
SATA_TX_C_P2: C6003.1 EL6001.4
SATA_TX_C_P3: C6004.1 EL6003.4
SATA_TX_C_P4: C6010.1 EL6006.4
SATA_TX_C_P5: C6014.1 EL6008.4
SATA_TX_CON_N2: C6002.2 SATA2.3 SATAEX1.S3
SATA_TX_CON_N3: C6005.2 SATA3.3 SATAEX1.S10
SATA_TX_CON_N4: C6013.2 SATA4.3
SATA_TX_CON_N5: C6017.2 SATA5.3
SATA_TX_CON_P2: C6003.2 SATA2.2 SATAEX1.S2
SATA_TX_CON_P3: C6004.2 SATA3.2 SATAEX1.S9
SATA_TX_CON_P4: C6010.2 SATA4.2
SATA_TX_CON_P5: C6014.2 SATA5.2
SATA_TX_PCH_N2: EL6001.2 PCH1.B39
SATA_TX_PCH_N3: EL6003.2 PCH1.A41
SATA_TX_PCH_N4: EL6006.2 PCH1.E45
SATA_TX_PCH_N5: EL6008.2 PCH1.G45
SATA_TX_PCH_P2: EL6001.1 PCH1.A39
SATA_TX_PCH_P3: EL6003.1 PCH1.A40
SATA_TX_PCH_P4: EL6006.1 PCH1.F45
SATA_TX_PCH_P5: EL6008.1 PCH1.G44
SATAEX_DET0: PCH1.AG39 R1709.2
SATAEX_DET1: PCH1.AD35 R1710.2
SATAEX_DET_CON: PU4003.G R1535.1 R6210.1 R31132.1 SATAEX1.P4
SATAEX_DET_CON_R: PU4003.D R1534.1 R1709.1 R1710.1 R6210.2
SATAEX_DEVSLP: PCH1.AE45 R1708.2
SATAEX_DEVSLP_CON: R1536.1 R1708.1 R1711.1 SATAEX1.P3
SENSE_A: R3001.2 R3012.2 R3013.2 U2701.13
SENSE_B: R2907.1 R2908.1 R2909.1 U2701.34
SIO_AGND: C447.2 C7901.2 C7908.2 C7911.2 C7912.2 C7913.2 C7914.2 C7925.2 C7927.2 R7953.2 R7954.1 R7959.2 R7964.2 R7969.2 RT2402.1 RT2403.1 SIO1.86 SIO1.87
SIO_AUDIO_MUTE: RN7901.1(A) SIO1.81
SIO_AVCC3: C7905.1 C7907.1 L7901.1 SIO1.99
SIO_CE_N: R7965.1 SIO1.30 U7902.1
SIO_CLK_DB: JP1.1 RN7902.2(A) SIO1.51
SIO_CTL1: Q3401.G R3402.2 R3408.2 SIO1.14
SIO_DAT_DB: JP1.2 RN7902.1(A) SIO1.52
SIO_EUP_EN: C7920.1 Q3514.G R3527.2 R7974.2
SIO_EUP_M: C3504.2 C3506.1 C3508.2 C3509.2 Q3508.G Q3509.G R3501.1
SIO_EUP_SELECT: R95.1 SIO1.60
SIO_HOLD#: R7947.1 U7902.7
SIO_MAIN_VCC3: R2480.1 R7950.1 SIO1.92
SIO_OCL_GREEN: R99.1 R653.1 SIO1.21
SIO_OCL_GREEN_R: Q23.2 R653.2 R6420.2
SIO_OCL_YELLOW: R98.1 SIO1.20
SIO_OCL_YELLOW_R: Q23.5 Q6807.G R652.2 R6421.2
SIO_PCIRSTIN#: R92.1 SIO1.3
SIO_PWM_LED_N: Q25.2 Q25.3 R64.2 SIO1.18
SIO_PWRLED_N: Q6401.S R6407.2 SIO1.27
SIO_SCK: C7909.1 R7948.1 R7951.2 U7902.6
SIO_SCK_R: R7951.1 SIO1.25
SIO_SI: R7949.1 SIO1.24 U7902.5
SIO_SO: R7966.1 SIO1.48 U7902.2
SIO_TUBRO_LED_N: Q6406.S R6412.2 R8001.1 SIO1.26
SIO_VCC_BLEED: Q98.D R1009.2 R2480.2
SIO_VCORE: C7918.2 C7919.1 SIO1.36
SIO_VDD_EN: RN7905.2(A) SIO1.84
SIO_VIN1: C447.1 R155.2 SIO1.97
SIO_VIN2: C7911.1 R7952.1 R7953.1 SIO1.96
SIO_VIN3: C7914.1 R7968.1 R7969.1 SIO1.95
SIO_VIN4: C7912.1 R7958.1 R7959.1 SIO1.94
SIO_VIN5: C7913.1 R7963.1 R7964.1 SIO1.93
SIO_VREF: C7901.1 R7997.2 R7998.2 SIO1.91
SIO_WP#: R7967.1 U7902.3
SIO_WRST#: C7903.1 R7938.2 SIO1.50
SKL_CNL_N: CPU1.AB36 TP_CPU_AB37.1
SKL_PCUSTB_0_DN: CPU1.E14 XDP1.6
SKL_PCUSTB_0_DP: CPU1.F14 XDP1.4
SKL_PCUSTB_1_DN: CPU1.G18 XDP1.24
SKL_PCUSTB_1_DP: CPU1.F18 XDP1.22
SLP_A#: PCH1.BC15 TP_PCH_BC1.1
SLP_LAN_N: R2478.1 R3110.2 R3160.1
SLP_LAN_N_C: PCH1.AV15 R3110.1
SLP_S3_A: Q3518.G R3526.1
SLP_S3_B: Q3515.E Q3518.D
SLP_S3_N: D4.A D21.2 PCH1.AW15 Q4302.G R985.1 R989.1 R3526.2 R4018.2 R4023.1 SIO1.71 U28.2 U3601.5 U3603.5 U3604.5 U3607.5
SLP_S4_N: PCH1.BD15 R85.1 R991.2 R4022.1 R4025.2 SIO1.77 U62.1 U4002.10
SLP_S4_N_R: Q72.2 R991.1
SLP_S4_N_SFR: C9.1 Q1.2 R85.2
SLP_S4_N_SFR_1: Q1.5 Q1.6 R77.2 R82.1
SLP_S4_N_SFR_2: Q1.3 R78.2 R81.1 R84.1
SLP_S4_N_SFR_G: C5.1 C6.1 Q2.G R84.2
SLP_SUS_N: PCH1.BB13 TP_PCH_N45.1
SLP_WLAN_N: PCH1.AV13 R2027.1
SM_DRAMRST#: PCH1.BC14 R2007.1
SM_DRAMRST#_R: C1143.1 C1144.1 C1145.1 C1146.1 C2007.1 DIMM1.58 DIMM2.58 DIMM3.58 DIMM4.58 R2007.2 R2053.2
SMB_CLK_MAIN: DIMM1.141 DIMM2.141 DIMM3.141 DIMM4.141 Q2004.S R2005.2 XDP1.53
SMB_CLK_MINI: NGFFE1.60 R6114.2
SMB_CLK_RESUME: C2004.2 PCH1.AW44 PCIE1.B5 PCIE2.B5 PCIE16.B5 Q2004.D R2002.2 R2477.1 R6114.1
SMB_DATA_MAIN: DIMM1.285 DIMM2.285 DIMM3.285 DIMM4.285 Q2007.S R2004.2 XDP1.51
SMB_DATA_MINI: NGFFE1.58 R6115.2
SMB_DATA_RESUME: C2003.2 PCH1.BB43 PCIE1.B6 PCIE2.B6 PCIE16.B6 Q2007.D R2003.2 R2476.1 R6115.1
SMBC_R2: R2477.2 SIO1.63
SMBD_R2: R2476.2 SIO1.64
SML1CLK_PCH: PCH1.AW42 R2019.1 TP_PCH_AW42.1
SML1DATA_PCH: PCH1.AW45 R2021.1 TP_PCH_AW45.1
SMLINK0_CLK: PCH1.AY44 R2016.1
SMLINK0_DATA: PCH1.BB39 R2018.1
SPI_CLK_PCH: PCH1.BC31 R2508.2
SPI_CLK_ROM: R2508.1 SPI1.6 U2501.6
SPI_CS_PCH_N0: PCH1.BD31 SPI1.1 U2501.1
SPI_HOLD_PCH: PCH1.BD30 R2208.2 R2209.2 R2506.2
SPI_HOLD_ROM: R2503.2 R2506.1 SPI1.7 U2501.7
SPI_SI_PCH: PCH1.BB29 R2202.2 R2203.2 R2510.2 R9906.1
SPI_SI_ROM: R2510.1 SPI1.5 U2501.5
SPI_SO_PCH: PCH1.BE30 R2204.2 R2205.2 R2505.1
SPI_SO_ROM: R2505.2 SPI1.2 U2501.2
SPI_WP_HW: R2512.1 WP1.2
SPI_WP_PCH: PCH1.BC29 R2206.2 R2207.2 R2507.1 R9914.2
SPI_WP_PCH_R: R9914.1 R9916.1 XDP1.60
SPI_WP_ROM: R2502.2 R2507.2 R2511.2 SPI1.3 U2501.3
SPI_WP_ROM_C: PCH1.AL44 R2509.1 U404.G
SPI_WP_ROM_C2: PCH1.AL36 R2512.2
SPI_WP_ROM_PLL: R2504.2 WP1.1
SPI_WP_SW: R2511.1 U404.D
SPKR: PCH1.BD26 R2008.1 R2010.1 R2210.2 R2211.2
SSD_SATA_DEVSLP: PCH1.AG42 R6215.2
SUS_STAT_N: PCH1.BC18 R1902.1
SUS_WARNB: PCH1.BD19 R2048.1 R2066.1 R2101.1 TP_SUS_WARNB.1
SUSACK_N: PCH1.BB19 R2045.1 R2101.2 TP_SUSACK_N.1
SUSCLK_PCH: PCH1.AN15 R2227.2 R6108.1 R6214.1
SUSCLK_PCH_M2: NGFFM1.68 R6214.2
SW_ON_N: PCH1.AT13 R7975.2 R9909.1
SW_ON_N_SIO: R96.1 R7975.1 R7977.1 SIO1.72
SYS_3VSB: R389.1 SIO1.70
SYS_FAN_3P_G: Q2601.C R2608.2 R2611.1 R2612.1
SYS_FAN_3P_G2: Q2606.C R2625.2 R2630.1 R2632.1
SYS_FAN_3P_POWER: FANS1.2 FANS2.2 Q2602.C Q2603.C R2609.1 R2616.2 TC2601.1
SYS_FAN_3P_POWER_2: FANS3.2 Q2604.C Q2605.C R2621.1 R2626.2 TC2602.1
SYS_FAN_FB: Q2601.E R2616.1 R2617.1
SYS_FAN_FB2: Q2606.E R2624.1 R2626.1
SYS_FAN_M: Q2602.B R2611.2
SYS_FAN_M1: Q2603.B R2612.2
SYS_FAN_M2: Q2604.B R2630.2
SYS_FAN_M12: Q2605.B R2632.2
SYS_FAN_PWM1: R2613.1 SIO1.11
SYS_FAN_PWM2: R2634.1 SIO1.13
SYS_FAN_TACH1: R2601.2 SIO1.10
SYS_FAN_TACH1_1: FANS1.3 FANS2.3 R2618.2 R2619.2
SYS_FAN_TACH1_2: R2601.1 R2619.1 R2620.1
SYS_FAN_TACH2: R2628.2 SIO1.12
SYS_FAN_TACH2_1: FANS3.3 R2622.2 R2623.2
SYS_FAN_TACH2_2: R2623.1 R2628.1 R2631.1
SYS_TMPIN: C7927.1 R7998.1 RT2403.2 SIO1.90
SYSTEM_FAN_PWM1_1: D2602.A FANS1.4 R2610.2 R2613.2 R2614.2
SYSTEM_FAN_PWM1_2: C2601.1 R2614.1 R2615.1
SYSTEM_FAN_PWM1_3: Q2601.B R2615.2
SYSTEM_FAN_PWM2_1: D2603.A FANS3.4 R2629.2 R2633.2 R2634.2
SYSTEM_FAN_PWM2_2: C2604.1 R2627.1 R2629.1
SYSTEM_FAN_PWM2_3: Q2606.B R2627.2
THERMTRIP#_CPU_R: CPU1.D11 R1704.2 R1707.1
THERMTRIP#_PCH: PCH1.AJ3 R1704.1
TP_3G16_JTAG1: PCIE16.B9 TP_3G16_JTAG5.1
TP_3G16_RSVD_A32: PCIE16.A32 TP_3G16_RSVD_A1.1
TP_3G16_RSVD_A33: PCIE16.A33 TP_3G16_RSVD_A2.1
TP_3G16_RSVD_A50: PCIE16.A50 TP_3G16_RSVD_A3.1
TP_3G16RSVD_A19: PCIE16.A19 TP_3G16RSVD_A1.1
TP_3G18_RSVD_B30: PCIE16.B30 TP_3G18_RSVD_B1.1
TP_16PRSNT_B82: PCIE16.B82 TP_16PRSNT_B1.1
TP_CPU7: CPU1.F37 TP_CPU7.1
TP_CPU9: CPU1.F36 TP_CPU9.1
TP_CPU10: CPU1.AK21 TP_CPU10.1
TP_CPU11: CPU1.AJ24 TP_CPU11.1
TP_CPU12: CPU1.AK22 TP_CPU12.1
TP_CPU_AC37: CPU1.AC37 TP_CPU_AC37.1
TP_CPU_AC38: CPU1.AC38 TP_CPU_AC38.1
TP_CPU_AC40: CPU1.AC40 TP_CPU_AC40.1
TP_CPU_AV1: CPU1.AV1 TP_CPU_AV1.1
TP_CPU_AV39: CPU1.AV39 TP_CPU_AV39.1
TP_CPU_AW2: CPU1.AW2 TP_CPU_AW2.1
TP_CPU_AW38: CPU1.AW38 TP_CPU_AW38.1
TP_CPU_G14: CPU1.G14 TP_CPU_G14.1
TP_CPU_H11: CPU1.H11 TP_CPU_H11.1
TP_CPU_H12: CPU1.H12 TP_CPU_H12.1
TP_CPU_H14: CPU1.H14 TP_CPU_H14.1
TP_CPU_J7: CPU1.J7 TP_CPU_J7.1
TP_CPU_J8: CPU1.J8 TP_CPU_J8.1
TP_CPU_K8: CPU1.K8 TP_CPU_K8.1
TP_CPU_K12: CPU1.K12 TP_CPU_K12.1
TP_CPU_L8: CPU1.L8 TP_CPU_L8.1
TP_CPU_L12: CPU1.L12 TP_CPU_L12.1
TP_DIMM1_PIN1: DIMM1.1 TP_DIMM_12V4.1
TP_DIMM2_PIN1: DIMM2.1 TP_DIMM_12V5.1
TP_DIMM3_PIN1: DIMM3.1 TP_DIMM_12V6.1
TP_DIMM4_PIN1: DIMM4.1 TP_DIMM_12V7.1
TP_DIMM_12V: DIMM1.145 TP_DIMM_12V.1
TP_DIMM_12V1: DIMM4.145 TP_DIMM_12V1.1
TP_DIMM_12V2: DIMM3.145 TP_DIMM_12V2.1
TP_DIMM_12V3: DIMM2.145 TP_DIMM_12V3.1
TP_PCH_AN17: PCH1.AN17 TP_PCH_AN17.1
TP_PCH_AN29: PCH1.AN29 TP_PCH_AN29.1
TP_PCH_AN43: PCH1.AN43 TP_PCH_AN43.1
TP_PCH_AN44: PCH1.AN44 TP_PCH_AN44.1
TP_PCH_AR19: PCH1.AR19 TP_PCH_AR19.1
TP_PCH_AR22: PCH1.AR22 TP_PCH_AR22.1
TP_PCH_AR39: PCH1.AR39 TP_PCH_AR39.1
TP_PCH_AR45: PCH1.AR45 TP_PCH_AR45.1
TP_PCH_BD14: PCH1.BD14 TP_PCH_BD14.1
TP_PCH_N29: PCH1.N29 TP_PCH_N29.1
TP_PCH_N31: PCH1.N31 TP_PCH_N31.1
TP_PCH_P24: PCH1.P24 TP_PCH_P24.1
TP_PCH_P27: PCH1.P27 TP_PCH_P27.1
TP_PCH_P29: PCH1.P29 TP_PCH_P29.1
TP_PCH_P31: PCH1.P31 TP_PCH_P31.1
TP_PCH_R24: PCH1.R24 TP_PCH_R24.1
TP_PCH_R27: PCH1.R27 TP_PCH_R27.1
TP_PCH_U13: PCH1.U13 TP_PCH_U13.1
TP_PCH_W13: PCH1.W13 TP_PCH_W13.1
TP_SLP_S5: PCH1.BA13 TP_SLP_S5.1
TPS2540_ILIM0: R3415.1 U3401.16
TPS2540_ILIM1: R3417.1 U3401.15
TURN_OFF_PWM: Q25.5 R64014.2 SIO1.23
U498_GATE: R476.1 U401.G U402.G U403.D
USB2_COMP: PCH1.AG3 R1604.1
USB2_ID: PCH1.AG2 R1606.1
USB2_VBUSSENSE: PCH1.AD10 R1605.1
USB20_OC_CR#: C3706.1 PCH1.Y43 R3703.2 R3704.1
USB20_OC_F1#: C3715.1 PCH1.W44 R3705.2 R3706.1
USB20_OC_F2#: C3701.1 PCH1.Y41 R1621.1 R3701.2 R3702.1
USB20_OC_RJUSB#: C3601.1 PCH1.W43 R3601.2 R3604.1
USB30_ID_PIN10: R3917.1 R3920.2 USB3F1.10
USB30_OC_H1#: PCH1.AD43 R3918.2 U3401.13
USB30_OC_H1#_R: C3901.1 R3916.2 R3918.1 R3919.1
USB30_OC_P1#: PCH1.AD42 R3815.1
USB30_OC_P1#_R: C3801.1 R3813.2 R3815.2 R3816.1
USB30_OC_P2#: PCH1.AD39 R1622.1
USB30_RX_CON_N1: EL3806.4 U3805.4 U3805.7 USB3R1.14
USB30_RX_CON_N2: EL3812.4 U3805.1 U3805.10 USB3R1.5
USB30_RX_CON_N3: EL3811.4 U3801.4 U3801.7 USB3R2.14
USB30_RX_CON_N4: EL3804.4 U3801.1 U3801.10 USB3R2.5
USB30_RX_CON_N5: EL3903.3 U3901.1 U3901.10 USB3F1.2
USB30_RX_CON_N6: EL3906.3 U3901.4 U3901.7 USB3F1.18
USB30_RX_CON_P1: EL3806.3 U3805.5 U3805.6 USB3R1.15
USB30_RX_CON_P2: EL3812.3 U3805.2 U3805.9 USB3R1.6
USB30_RX_CON_P3: EL3811.3 U3801.5 U3801.6 USB3R2.15
USB30_RX_CON_P4: EL3804.3 U3801.2 U3801.9 USB3R2.6
USB30_RX_CON_P5: EL3903.4 U3901.2 U3901.9 USB3F1.3
USB30_RX_CON_P6: EL3906.4 U3901.5 U3901.6 USB3F1.17
USB30_RX_PCH_N1: EL3806.2 PCH1.B7
USB30_RX_PCH_N2: EL3812.2 PCH1.C8
USB30_RX_PCH_N3: EL3811.2 PCH1.B10
USB30_RX_PCH_N4: EL3804.2 PCH1.E11
USB30_RX_PCH_N5: EL3903.1 PCH1.G13
USB30_RX_PCH_N6: EL3906.1 PCH1.K15
USB30_RX_PCH_P1: EL3806.1 PCH1.A7
USB30_RX_PCH_P2: EL3812.1 PCH1.B8
USB30_RX_PCH_P3: EL3811.1 PCH1.A9
USB30_RX_PCH_P4: EL3804.1 PCH1.G11
USB30_RX_PCH_P5: EL3903.2 PCH1.H13
USB30_RX_PCH_P6: EL3906.2 PCH1.K13
USB30_TX_CMC_N1: EC3801.2 EL3801.2
USB30_TX_CMC_N2: EC3806.2 EL3809.2
USB30_TX_CMC_N3: EC3807.2 EL3810.2
USB30_TX_CMC_N4: EC3802.2 EL3803.2
USB30_TX_CMC_N5: EC3902.2 EL3902.1
USB30_TX_CMC_N6: EC3901.2 EL3901.1
USB30_TX_CMC_P1: EC3804.2 EL3801.1
USB30_TX_CMC_P2: EC3808.2 EL3809.1
USB30_TX_CMC_P3: EC3805.2 EL3810.1
USB30_TX_CMC_P4: EC3803.2 EL3803.1
USB30_TX_CMC_P5: EC3903.2 EL3902.2
USB30_TX_CMC_P6: EC3904.2 EL3901.2
USB30_TX_CON_N1: EL3801.4 U3806.1 U3806.10 USB3R1.17
USB30_TX_CON_N2: EL3809.4 U3806.4 U3806.7 USB3R1.8
USB30_TX_CON_N3: EL3810.4 U3802.1 U3802.10 USB3R2.17
USB30_TX_CON_N4: EL3803.4 U3802.4 U3802.7 USB3R2.8
USB30_TX_CON_N5: EL3902.3 U3902.1 U3902.10 USB3F1.5
USB30_TX_CON_N6: EL3901.3 U3902.4 U3902.7 USB3F1.15
USB30_TX_CON_P1: EL3801.3 U3806.2 U3806.9 USB3R1.18
USB30_TX_CON_P2: EL3809.3 U3806.5 U3806.6 USB3R1.9
USB30_TX_CON_P3: EL3810.3 U3802.2 U3802.9 USB3R2.18
USB30_TX_CON_P4: EL3803.3 U3802.5 U3802.6 USB3R2.9
USB30_TX_CON_P5: EL3902.4 U3902.2 U3902.9 USB3F1.6
USB30_TX_CON_P6: EL3901.4 U3902.5 U3902.6 USB3F1.14
USB30_TX_PCH_N1: EC3801.1 PCH1.C11
USB30_TX_PCH_N2: EC3806.1 PCH1.B12
USB30_TX_PCH_N3: EC3807.1 PCH1.C13
USB30_TX_PCH_N4: EC3802.1 PCH1.A14
USB30_TX_PCH_N5: EC3902.1 PCH1.B14
USB30_TX_PCH_N6: EC3901.1 PCH1.B15
USB30_TX_PCH_P1: EC3804.1 PCH1.B11
USB30_TX_PCH_P2: EC3808.1 PCH1.A12
USB30_TX_PCH_P3: EC3805.1 PCH1.D13
USB30_TX_PCH_P4: EC3803.1 PCH1.B13
USB30_TX_PCH_P5: EC3903.1 PCH1.C14
USB30_TX_PCH_P6: EC3904.1 PCH1.C15
USB_CON_PN1: EL3802.2 U3804.6 USB3R1.11
USB_CON_PN2: EL3808.2 U3804.3 USB3R1.2
USB_CON_PN3: EL3807.2 U3803.3 USB3R2.11
USB_CON_PN4: EL3805.2 U3803.1 USB3R2.2
USB_CON_PN5: EL3603.3 U2RJ1.U6 U3602.4
USB_CON_PN6: EL3604.3 U2RJ1.U2 U3602.6
USB_CON_PN7: EL3904.3 U3903.1 USB3F1.8
USB_CON_PN8: EL3905.3 U3903.4 USB3F1.12
USB_CON_PN9: CRF1.4 EL3703.2 U3702.6
USB_CON_PN10: EL3605.4 NGFFE1.5
USB_CON_PN11: EL3702.3 U3701.6 USB2F2.7
USB_CON_PN12: EL3701.3 U3701.4 USB2F2.8
USB_CON_PP1: EL3802.3 U3804.1 USB3R1.12
USB_CON_PP2: EL3808.3 U3804.4 USB3R1.3
USB_CON_PP3: EL3807.3 U3803.4 USB3R2.12
USB_CON_PP4: EL3805.3 U3803.6 USB3R2.3
USB_CON_PP5: EL3603.2 U2RJ1.U7 U3602.3
USB_CON_PP6: EL3604.2 U2RJ1.U3 U3602.1
USB_CON_PP7: EL3904.2 U3903.6 USB3F1.9
USB_CON_PP8: EL3905.2 U3903.3 USB3F1.11
USB_CON_PP9: CRF1.3 EL3703.3 U3702.1
USB_CON_PP10: EL3605.1 NGFFE1.3
USB_CON_PP11: EL3702.2 U3701.1 USB2F2.5
USB_CON_PP12: EL3701.2 U3701.3 USB2F2.6
USB_F_D: Q3402.D R3167.1 R3168.2
USB_F_EN: C3143.1 Q3109.G R3168.1
USB_PCH_PN1: EL3802.1 PCH1.AF5
USB_PCH_PN2: EL3808.1 PCH1.AD5
USB_PCH_PN3: EL3807.1 PCH1.AG8
USB_PCH_PN4: EL3805.1 PCH1.AE1
USB_PCH_PN5: EL3603.4 PCH1.AC2
USB_PCH_PN6: EL3604.4 PCH1.AF2
USB_PCH_PN7: PCH1.AB3 R3412.1 U3401.2
USB_PCH_PN8: EL3905.4 PCH1.AL8
USB_PCH_PN9: EL3703.1 PCH1.AA1
USB_PCH_PN10: EL3605.3 PCH1.AJ8
USB_PCH_PN11: EL3702.4 PCH1.W2
USB_PCH_PN12: EL3701.4 PCH1.AD3
USB_PCH_PP1: EL3802.4 PCH1.AG7
USB_PCH_PP2: EL3808.4 PCH1.AD7
USB_PCH_PP3: EL3807.4 PCH1.AG10
USB_PCH_PP4: EL3805.4 PCH1.AE2
USB_PCH_PP5: EL3603.1 PCH1.AC3
USB_PCH_PP6: EL3604.1 PCH1.AF3
USB_PCH_PP7: PCH1.AB2 R3413.1 U3401.3
USB_PCH_PP8: EL3905.1 PCH1.AL7
USB_PCH_PP9: EL3703.4 PCH1.AA2
USB_PCH_PP10: EL3605.2 PCH1.AJ7
USB_PCH_PP11: EL3702.1 PCH1.W3
USB_PCH_PP12: EL3701.1 PCH1.AD2
USB_PCH_U_PN7: EL3904.4 R3412.2 U3401.11
USB_PCH_U_PP7: EL3904.1 R3413.2 U3401.10
V_3P3_DBP: DBGH1.4 R6801.2
V_5_PWR1: L6401.2 R64013.1
V_CPU_ST_PLL_R: R73.2 R74.1 R76.2
V_SM_R2_DIMM_VREF_A: R1125.1 R1129.2 R1130.2
V_SM_VREF_CNT: C3.1 C1134.1 CPU1.AB40 R1126.1
VCORE_PG: D20.1 PU4601.54 R2012.1 R4693.1
VIDALERT#_CPU: CPU1.E39 R469.2
VIDALERT#_VR1: PR4681.2 PR4692.1 R469.1 R470.1
VIDSCK_CPU: CPU1.E38 R402.2
VIDSCK_VR1: PR4670.2 PR4679.2 R402.1
VIDSOUT_CPU: CPU1.E40 R406.2 R471.1
VIDSOUT_VR1: PR4680.1 PR4691.2 R406.1
VISACH2_D3: PCH1.AC44 R2201.2 R2225.2
VPP_EN: PC5040.1 PR977.1 R984.1 R4011.2
VPP_EN_CR: Q73.C R980.2 R984.2
VPP_EN_DDR4: Q72.3 Q72.6 Q73.B R979.2
VPP_EN_R: R4011.1 U4002.4
VPP_PG: PC5041.1 PR5144.2 PU51.4 R988.1 R4014.2 R4021.1 U62.2
VPP_R: R4010.1 R4014.1 U4002.2
VR_ENABLE: PC4655.1 PR4682.1 PR5320.2 PU4601.27 R533.2 R695.2 R5204.2 R5205.1 U5202.G
VRALERTB_PU: PCH1.BD23 R2023.1
VRD_TMPIN: C7925.1 R7997.1 RT2402.2 SIO1.89
VRMPWG_G: C420.2 D20.3 R478.1 R699.2 U403.G
VRMPWG_G_R: R699.1 U28.3
VTT_A: R985.2 R987.2 U63.1
VTT_B: R988.2 R989.2 U63.2
VTT_EN: C775.1 PU5002.7 R982.1 R4015.2 R4023.2
VTT_EN_CR: R982.2 R986.2 U63.4
VTT_EN_R: R4015.1 U4002.5
W1_DISABLE_N: NGFFE1.56 R6110.1 R6117.2 R8013.1 SIO1.83
W3_DISABLE_N: NGFFE1.54 R6105.1 R6116.2 R8014.1 SIO1.82
WLAN_CLK_CON: NGFFE1.42 R6102.2
WLAN_CLK_PCH: PCH1.AV2 R6102.1
WLAN_DAT_CON: NGFFE1.40 R6103.2
WLAN_DAT_PCH: PCH1.AV3 R6103.1
WLAN_RST_CON: NGFFE1.38 R6104.2
WLAN_RST_PCH: PCH1.AW2 R6104.1
XCLK_BIASREF_PCH: PCH1.E1 R1803.2
XDP_CLK_CON: PCH1.L2 XDP1.40
XDP_CLK_CON#: PCH1.L1 XDP1.42
XDP_HOOK0: R9902.2 R9903.2 R9904.2 XDP1.39
XDP_HOOK1: R9909.2 XDP1.41
XDP_HOOK2: R9913.2 R9915.1 XDP1.45
XDP_HOOK3: C9902.2 R9905.1 R9906.2 R9908.2 XDP1.47
XDP_HOOK6: R9917.2 R9918.1 R9919.2 XDP1.46
XDP_PCUDEBUG3: R414.2 R9901.1 XDP1.1
XTL_24M_IN_PCH: C1802.1 PCH1.A6 R1807.1 X1802.3
XTL_24M_OUT_PCH: C1803.1 PCH1.A5 R1807.2 X1802.1
XTL_32K_X1_PCH: C1801.1 PCH1.BC9 R1808.1 X1801.1
XTL_32K_X2_PCH: C1804.1 PCH1.BD10 R1808.2 X1801.4

Pads without a net: ATX1 20; AUDF1 7; CMOS1 1; CPU1 A14 A16 AL25 AL26 AM25 AM26 AN25 AN26 AP25 AP26 AR25 AR26 AT33 AU9 AU10 AU31 AU32 AU33 AU39 AU40 AV31 AV32 AV33 AW31 AW33 AY31 B11 B13 B14 B15 B16 B17 B39 C9 C11 C13 C15 C17 C40 D9 D10 D12 D14 D15 E10 E12 F9 G9 G10 H10 J11 J13 J14 J15 J17 J19 K10 K11 L10; CRF1 1; D21 1; DBGH1 5 11 13; DIMM1 8 19 30 41 47 49 52 54 56 93 100 111 122 133 144 192 194 196 197 199 201 205 227 230 234 235 237; DIMM2 8 19 30 41 47 49 52 54 56 93 100 111 122 133 144 192 194 196 197 199 201 205 227 230 234 235 237; DIMM3 8 19 30 41 47 49 52 54 56 93 100 111 122 133 144 192 194 196 197 199 201 205 227 230 234 235 237; DIMM4 8 19 30 41 47 49 52 54 56 93 100 111 122 133 144 192 194 196 197 199 201 205 227 230 234 235 237; ED3204 6; ED5603 5 6; HDMI1 13 14; LEDH1 9 10 13; LEDH2 1; MECLR1 1; NGFFE1 6 8 9 10 11 12 13 14 15 16 17 19 20 21 22 23 32 34 36 44 46 48 59 61 64 65 66 67 68 70 71 73 76 77; NGFFM1 6 8 20 22 24 26 28 30 32 34 36 40 42 44 46 48 56 58 67; PCH1 A16 A21 AA44 AA45 AB33 AB35 AB36 AB39 AB41 AB42 AB43 AB44 AC43 AD31 AD38 AE17 AF17 AG14 AG15 AG35 AG43 AG44 AH43 AH44 AJ11 AJ13 AJ33 AJ35 AJ38 AJ42 AJ43 AJ44 AK44 AK45 AL27 AL39 AL42 AL43 AM43 AN24 AN36 AN38 AN41 AN42 AR24 AR27 AR29 AR31 AR38 AR41 AR44 AT31 AT42 AT44 AU41 AU43 AU44 AV4 AV29 AV43 AV44 AW27 AW31 AW33 AW35 B16 B19 B20 B21 B36 B38 BA4 BA33 BA35 BA41 BB17 BB22 BB24 BB31 BB33 BB36 BB38 BC8 BC19 BC22 BC23 BC26 BC27 BC32 BC33 BC35 BC36 BC38 BD1 BD18 BD21 BD22 BD24 BD27 BD33 BD34 BD36 BD38 BD39 BE2 BE21 BE34 BE39 C19 C20 C36 C38 D39 E17 E20 E35 E37 G15 G17 G19 G35 H15 H43 H44 J45 K17 K44 L17 L37 L39 M44 M45 N2 N3 N7 N8 N38 N39 N42 N43 N44 P1 P2 P3 P43 P44 R2 R3 R4 R7 R8 R11 R13 R35 R39 R41 R42 R43 R44 T44 T45 U2 U3 U5 U7 U36 U39 U41 U42 U43 V1 V2 V44 W7 W35 W36 W39 W42 Y5; PCIE1 A5 A6 A7 A8 B9 B12; PCIE2 A5 A6 A7 A8 B9 B12; PCIE16 A5 A6 A7 A8 B12; PU51 7; PU4601 16 28 30 44 48 56; SATAEX1 P1; SIO1 1 6 16 29 31 53 54 56 58 59 61 62 65 66 78 88 100 101 102 103 104 105 106 107 108 109 110 111 112 113 114 115 116 117 118 119 120 121 122 123 124 125 126 127 128; SPK1 4; U2701 2 12 18 19 20 33 37 43 44 45 46 48; U3401 9; U3601 6; U3603 6; U3604 6; U3605 3; U3606 3; U3607 6; U3608 3; U3702 3 4; U4002 12; USB2F2 1; USB3F1 20

Small or netless copper shapes (teardrops, artwork), in the pictures only: 8 on TOP, 8 on BOTTOM

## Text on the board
User.Comments: JOJO_1117
Ref Des/Silkscreen Top: X3101:25MHZ | F5601:1.5A/8V | X1802:24MHZ | X1801:32.768KHZ | F5602:1.5A/8V | MIB15L-SophiaB | 14069-1 | 348.02E01.0011 | MADE IN TAIWAN
User.21: Board Accuracy Check,Aug 07 14:28:58 2015,Passed | Component Overlap Check,Dec 19 16:53:44 2014,33 errors | Dummy-Static-No Shape On Layer Check,Aug 07 14:28:59 2015,7 errors | Split Plane Check,Aug 07 14:28:58 2015,7 errors
User.23: ByImpedance:100.0@_REF_L1=("4.0/12.0(L1)")|Type="DP"|_REF_L4=("4.0/12.0(L4)")|_REF_L3=("nil(L3)")|imp="100.0" | ByImpedance:32.0@_REF_L1=("9.5(L1)")|Type="SE"|_REF_L4=("9.5(L4)")|_REF_L3=("9.0(L3)")|imp="32.0" | ByImpedance:34.0@_REF_L1=("9.0(L1)")|Type="SE"|_REF_L4=("9.0(L4)")|_REF_L3=("8.0(L3)")|imp="34.0" | ByImpedance:35.0@_REF_L1=("8.5(L1)")|Type="SE"|_REF_L4=("8.5(L4)")|_REF_L3=("7.5(L3)")|imp="35.0" | ByImpedance:37.5@_REF_L1=("7.5(L1)")|Type="SE"|_REF_L4=("7.5(L4)")|_REF_L3=("7.0(L3)")|imp="37.5" | ByImpedance:39.0@_REF_L1=("7.0(L1)")|Type="SE"|_REF_L4=("7.0(L4)")|_REF_L3=("6.5(L3)")|imp="39.0" | ByImpedance:40.0@_REF_L1=("6.5(L1)")|Type="SE"|_REF_L4=("6.5(L4)")|_REF_L3=("6.0(L3)")|imp="40.0" | ByImpedance:42.0@_REF_L1=("6.0(L1)")|Type="SE"|_REF_L4=("6.0(L4)")|_REF_L3=("5.5(L3)")|imp="42.0" | ByImpedance:45.0@_REF_L1=("5.0(L1)")|Type="SE"|_REF_L4=("5.0(L4)")|_REF_L3=("4.5(L3)")|imp="45.0" | ByImpedance:50.0@_REF_L1=("4.0(L1)")|Type="SE"|_REF_L4=("4.0(L4)")|_REF_L3=("4.0(L3)")|imp="50.0" | ByImpedance:62.0@_REF_L1=("8.5/5.0(L1)")|Type="DP"|_REF_L4=("8.5/5.0(L4)")|_REF_L3=("7.5/5.0(L3)")|imp="62.0" | ByImpedance:65.0@_REF_L1=("8.0/5.0(L1)")|Type="DP"|_REF_L4=("8.0/5.0(L4)")|_REF_L3=("7.0/5.5(L3)")|imp="65.0" | ByImpedance:70.0@_REF_L1=("7.0/5.0(L1)")|Type="DP"|_REF_L4=("7.0/5.0(L4)")|_REF_L3=("6.0/5.0(L3)")|imp="70.0" | ByImpedance:72.0@_REF_L1=("7.0/7.0(L1)")|Type="DP"|_REF_L4=("7.0/7.0(L4)")|_REF_L3=("5.5/5.0(L3)")|imp="72.0" | ByImpedance:80.0@_REF_L1=("6.0/9.0(L1)" "5.0/5.0(L1)")|Type="DP"|_REF_L4=("6.0/9.0(L4)" "5.0/5.0(L4)")|_REF_L3=("4.5/6.0(L3)")|imp="80.0" | ByImpedance:85.0@_REF_L1=("4.0/4.5(L1)" "5.0/7.0(L1)")|Type="DP"|_REF_L4=("4.0/4.5(L4)" "5.0/7.0(L4)")|_REF_L3=("4.0/6.0(L3)")|imp="85.0" | ByImpedance:90.0@_REF_L1=("4.0/6.0(L1)")|Type="DP"|_REF_L4=("4.0/6.0(L4)")|_REF_L3=("4.0/9.0(L3)")|imp="90.0" | ByImpedance:95.0@_REF_L1=("4.0/8.0(L1)")|Type="DP"|_REF_L4=("4.0/8.0(L4)")|_REF_L3=("nil(L3)")|imp="95.0" | LayerIndex:nil | Source:4-1.6-8d.xls | artWorks:("_REF_L3" "_REF_L4" "_REF_L1") | gtImpOutlineUsed:BOARD GEOMETRY/OUTLINE
User.25: This gerber is just for your reference to find the DP impedance traces in layer L1. | DP IMPEDANCE TABLE: L1 | * - Denotes that WIDTH | is NOT used in this layer | inside board outline. | IMP(Ohm) | 62.0 | 65.0 | 70.0 | 72.0 | 80.0 | 85.0 | 90.0 | 95.0 | 100.0 | WIDTH(mils) | 8.5/5.0 | 8.0/5.0 | *7.0/5.0 | *7.0/7.0 | *6.0/9.0 | *5.0/5.0 | 4.0/4.5 | *5.0/7.0 | 4.0/6.0 | *4.0/8.0 | 4.0/12.0 | TYPE | DP
User.27: This gerber is just for your reference to find the SE impedance traces in layer L1. | SE IMPEDANCE TABLE: L1 | * - Denotes that WIDTH | is NOT used in this layer | inside board outline. | IMP(Ohm) | 32.0 | 34.0 | 35.0 | 37.5 | 39.0 | 40.0 | 42.0 | 45.0 | 50.0 | WIDTH(mils) | *9.5 | *9.0 | 8.5 | *7.5 | *7.0 | 6.5 | 6.0 | 5.0 | 4.0 | TYPE | SE
User.29: This gerber is just for your reference to find the DP impedance traces in layer L3. | DP IMPEDANCE TABLE: L3 | * - Denotes that WIDTH | is NOT used in this layer | inside board outline. | IMP(Ohm) | 62.0 | 65.0 | 70.0 | 72.0 | 80.0 | 85.0 | 90.0 | 95.0 | 100.0 | WIDTH(mils) | 7.5/5.0 | 7.0/5.5 | *6.0/5.0 | *5.5/5.0 | *4.5/6.0 | *4.0/6.0 | *4.0/9.0 | *nil | TYPE | DP
User.31: This gerber is just for your reference to find the SE impedance traces in layer L3. | SE IMPEDANCE TABLE: L3 | * - Denotes that WIDTH | is NOT used in this layer | inside board outline. | IMP(Ohm) | 32.0 | 34.0 | 35.0 | 37.5 | 39.0 | 40.0 | 42.0 | 45.0 | 50.0 | WIDTH(mils) | *9.0 | *8.0 | 7.5 | *7.0 | *6.5 | 6.0 | 5.5 | *4.5 | 4.0 | TYPE | SE
User.33: This gerber is just for your reference to find the DP impedance traces in layer L4. | DP IMPEDANCE TABLE: L4 | * - Denotes that WIDTH | is NOT used in this layer | inside board outline. | IMP(Ohm) | 62.0 | 65.0 | 70.0 | 72.0 | 80.0 | 85.0 | 90.0 | 95.0 | 100.0 | WIDTH(mils) | *8.5/5.0 | *8.0/5.0 | *7.0/5.0 | *7.0/7.0 | *6.0/9.0 | *5.0/5.0 | 4.0/4.5 | *5.0/7.0 | *4.0/6.0 | *4.0/8.0 | 4.0/12.0 | TYPE | DP
User.35: This gerber is just for your reference to find the SE impedance traces in layer L4. | SE IMPEDANCE TABLE: L4 | * - Denotes that WIDTH | is NOT used in this layer | inside board outline. | IMP(Ohm) | 32.0 | 34.0 | 35.0 | 37.5 | 39.0 | 40.0 | 42.0 | 45.0 | 50.0 | WIDTH(mils) | *9.5 | *9.0 | *8.5 | *7.5 | *7.0 | *6.5 | *6.0 | 5.0 | 4.0 | TYPE | SE
User.39: AGND | 1D05V_VLAN | GND | 5V_AUX | 12V_S0 | 5V_S0 | PWR_+VCORE_VIN | 12V_CPU_S0 | PWR_RT9624F_SW1 | PWR_RT9624F_SW2 | PWR_RT9624F_SW3 | PWR_RT9624F_SW4 | PWR_VCCSA_VIN | PWR_VCCSA_LX | 0D95V_VCCSA_S0 | PWR_+VGT_VIN | 3D3V_S0 | PWR_RT9624F_SW1A | PWR_+0P95V_PHASE | 0D95V_VCCIO_S0 | PWR_RT9624F_SW2A | 2D5V_VPP_S3 | 1D2V_VDDQ_S3
User.41: This gerber is just for you reference to find the differential traces in layer TOP
User.42: This gerber is just for you reference to find the differential traces in layer BOTTOM
User.43: This gerber is just for you reference to find the differential traces in layer L3
User.45: Note:Refer to DRILL layer for ELLIPSE drill direction | FIGURE | SIZE | 8.0 | 10.0 | 12.0 | 16.0 | 20.0 | 25.0 | 26.0 | 28.0 | 29.0 | 30.0 | 32.0 | 35.0 | 36.0 | 37.0 | 39.0 | 40.0 | 45.0 | 52.0 | 54.0 | 56.0 | 60.0 | 68.0 | 91.0 | 109.0 | 113.0 | 46.0 | 65.0 | 86.0 | 93.0 | 97.0 | 119.0 | 150.0 | 158.0 | 159.0 | 67.0x24.0 | 83.0x36.0 | 87.0x24.0 | 107.0x36.0 | 97.0x48.0 | DRILL CHART: TOP to BOTTOM | ALL UNITS ARE IN MILS | PLATED | NON-PLATED | QTY | 548 | 797 | 2528 | 1088 | 64 | 14 | 1152 | 36 | 236 | 32 | 19 | 15 | 8 | 96 | 80 | 12 | 2 | 10 | 28 | 4 | 20 | 1 | 6 | 3 | Model | MIB15L-SophiaB | PCB_NO | 14069 | VER. | Layer | DRILL | L1 | L2 | TMASK | TPLACE | TSILK | TSMD | Designer | CATHY | Date | 08/07/2015 | BMASK | BPLACE | BSILK | BSMD | L3 | L4
